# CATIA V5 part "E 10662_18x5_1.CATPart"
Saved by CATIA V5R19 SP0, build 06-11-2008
Part number: E 10662_18x5_1
Definition: E 10662_18x5_1
Nomenclature: E 10662_18x5_1
Source: Unknown
Description: PART--DESC
Bounding box of the stored display mesh (mm): x -34 to -16, y -9 to 9, z -49.9 to -45
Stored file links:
  C:\Users\jsmid\Desktop\DP_Smidak_Forma LEGO\E 10662_18x5_1.CATPart
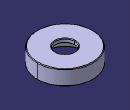
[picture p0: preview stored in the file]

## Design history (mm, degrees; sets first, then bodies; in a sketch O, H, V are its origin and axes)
Body1 "E 10662_18x5" (main body)
  Solid1: solid without history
